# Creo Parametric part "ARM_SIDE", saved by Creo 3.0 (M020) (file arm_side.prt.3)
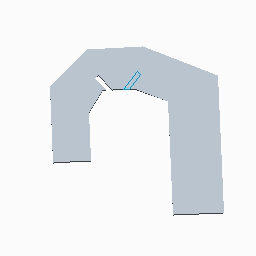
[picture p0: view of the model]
Units: millimeter Newton Second (mmNs); MM, TONNE, SECS

Created from: MMNS_PART_SOLID.PRT

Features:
  1. datum plane "RIGHT"
  2. datum plane "TOP"
  3. datum plane "FRONT"
  4. coordinate system
  5. sketch "Sketch 1"
  6. extrusion "Extrude 1"
  7. sketch "Sketch 2"
  8. sketch "Sketch 3"
  9. extruded cut "Extrude 3"
  10. sketch "Sketch 4"

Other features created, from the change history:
  datum plane "DTM1"
  sketch "Sketch 2"
  extruded cut "Extrude 2"
  extruded cut "Extrude 3"

Surfaces: 21 plane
